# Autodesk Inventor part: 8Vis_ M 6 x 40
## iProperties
Created: 2011-01
Part Number: 8Vis_ M 6 x 40
Document SubType Name: Modeling
Designer: eric
Density: 1 g/cm^3
Mass: 1.54113 g
Surface Area: 12.9148 cm^2
Volume: 1.54113 cm^3
Author: eric
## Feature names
1. Base1
